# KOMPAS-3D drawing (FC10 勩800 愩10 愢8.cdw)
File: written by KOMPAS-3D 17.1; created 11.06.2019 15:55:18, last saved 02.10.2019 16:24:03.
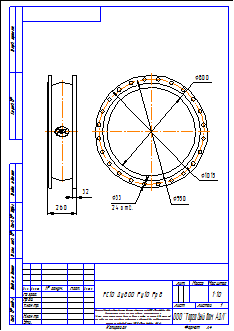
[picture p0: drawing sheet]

Sheet 1: A4, portrait

Title block, sheet 1: name: FC10 Ду800 Ру10 Рр8; material: Сталь 20  ГОСТ 1050-2013; sheets: 1; sheet format: A4; stored path: \\adlc.lan\data\АДЛ_ПКД\3D-модели\ADL production\Гибкие вставки серии FC\FC10\KOMPAS 2D\FC10 Ду800 Ру10 Рр8.cdw

Views: Вид 1
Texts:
  kka
  adl
  Рама для чертежей
  Лит-Масса-Масштаб
  Материал-Предприятие
  Масштаб
  Изм.
  Лист
  № докум.
  Подп.
  Дата
  Лит.
  Разраб.
  Пров.
  Т.контр.
  Листов
  Внимание! Данный продукт является объектом авторского права ООО «Торговый Дом АДЛ».
  Запрещается изменение, копирование, распространение
  (в том числе путем копирования на другие сайты и ресурсы в Интернете)
  или любое иное использование информации и объектов без предварительного
  согласия правообладателя (ООО «Торговый Дом АДЛ»).
  Н.контр.
  Утв.
  ООО "Торговый дом АДЛ"
  Изменение
  Номер документа
  Подпись
  Обозначение документа
  Наименование изделия
  Масса изделия по ГОСТ 2.109-73
  Порядковый номер листа
  Общее количество листов в документе
  Характер работы, выполненной лицом, подписавшим документ
  Наименование или индекс предприятия, выпускающего документ
  Инв. № подл.
  Подп. и дата
  Взам. инв. №
  Инв. № дубл.
  Инвентарный номер подлинника по ГОСТ 2.501-68
  Подпись принявшего подлинник в отдел технической документации
  Инвентарный номер подлинника, взамен которого выпущен данный подлинник
  Инвентарный номер дубликата по ГОСТ 2.502-68
  Подпись принявшего дубликат в отдел технической документации
  Справ. №
  Перв. примен.
  Обозначение документа, взамен или на основании которого выпущен данный документ
  Обозначение документа, в котором впервые записан данный документ
  Подпись лица, копировавшего чертеж
  Обозначение формата листа
  !Рама для чертежа
Dimensions and other numbers on the sheet: 32; 260; 1:10; 1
